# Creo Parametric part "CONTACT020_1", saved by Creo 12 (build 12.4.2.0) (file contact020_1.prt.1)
Units: Custom; MM, KILOGRAM, SECS

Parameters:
  PTC_WM_ITERATION = "0"
  PTC_WM_VERSION = "-.0"
  PTC_WM_LIFECYCLE_STATE = "In Work"
  PTC_WM_LIFECYCLE = "MO_CADDocument"
  PTC_WM_CREATED_BY = "Maximilian Roepper (Z0017RMS: MO)"
  PTC_WM_CREATED_ON = "18-Sep-26 11:36:42 AM"
  PTC_WM_MODIFIED_BY = "Maximilian Roepper (Z0017RMS: MO)"
  PTC_WM_MODIFIED_ON = "18-Sep-26 11:36:46 AM"
  PDMLINKNUMBER = "PDM000071454986"
  PTC_WM_NAME = "contact020_1.prt"
  PTC_WM_NUMBER = "PDM000071454986"

Other parameters: WEIGHT, WEIGHT_FACTOR, WEIGHT_ADD, _MASS_TEMP, _DIFF_TEMP, MC_ERRORS, SUPPLIER

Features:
  1. coordinate system
  2. datum plane "PRT_YZ"
  3. datum plane "PRT_XY"
  4. datum plane "PRT_XZ"
  5. coordinate system
  6. datum axis
  7. datum axis
  8. datum axis
  9. coordinate system
  10. imported feature

Other named items: PRT, SIEMENS_MO, DRW_VIEW_ORG, PRT_X, PRT_Y, PRT_Z, CS0, ROUGH_GROB

Layers: 00_STD_CSYS-KSYS, 01_STD_PLANES-EBENEN, 02_STD_AXES-ACHSEN, 03_STD_CSYS-KSYS, 24_IMPORT_FEAT-IMPORT_KE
